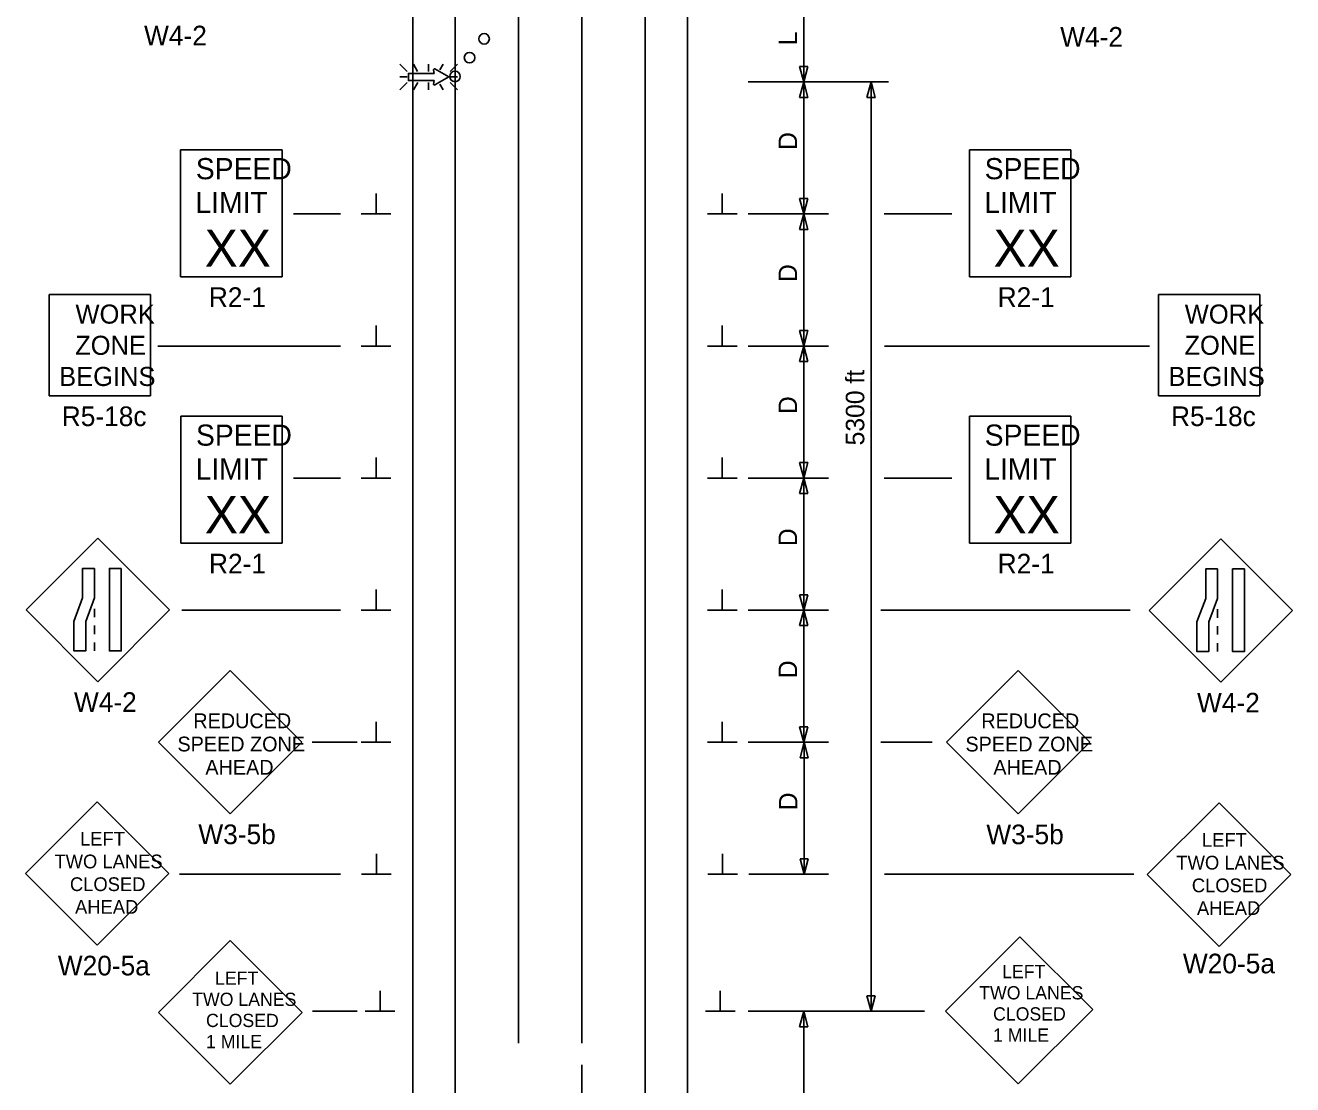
# Model space of a CAD drawing. Extents: x 16553 to 18478, y 5759 to 7026.
# Drawn here: x 16725.1 to 17204.7, y 6181.4 to 6582.5 of the extents above; entities that cross this region are included whole.
import ezdxf

# ---------------------------------------------------------------- set-up
doc = ezdxf.new("R2010")
doc.units = 0
for name, color, linetype in [('ALI_LEGAL_EX', 7, 'Continuous'), ('PAVT_EDGE_EX', 7, 'Continuous'), ('TRAFFIC_SIGNS_PR', 7, 'Continuous'), ('TYPICAL_TEXT_DIMEN_PR', 7, 'Continuous')]:
    doc.layers.add(name, color=color, linetype=linetype)

msp = doc.modelspace()

# ---------------------------------------------------------------- linework, layer by layer
at = {"layer": 'ALI_LEGAL_EX'}
for p, q in [((16911.66, 7026.35), (16911.66, 6197.16)), ((16935.66, 7026.35), (16935.66, 6197.16)), ((16935.66, 7026.35), (16935.66, 6197.16))]:
    msp.add_line(p, q, dxfattribs=at)
for points in [[(16911.66, 6526.35), (16911.66, 6501.35)], [(16935.66, 6526.35), (16935.66, 6501.35)], [(16911.66, 6426.35), (16911.66, 6401.35)], [(16935.66, 6426.35), (16935.66, 6401.35)], [(16911.66, 6326.35), (16911.66, 6301.35)], [(16935.66, 6326.35), (16935.66, 6301.35)], [(16911.66, 6226.35), (16911.66, 6201.35)], [(16935.66, 6226.35), (16935.66, 6201.35)], [(16935.66, 6163.99), (16935.66, 6188.99)]]:
    msp.add_lwpolyline(points, dxfattribs=at)
at = {"layer": 'PAVT_EDGE_EX'}
for p, q in [((16871.66, 6926.66), (16871.66, 6223.96)), ((16887.66, 6926.66), (16887.66, 6223.96)), ((16959.66, 6926.66), (16959.66, 6223.96)), ((16975.66, 6926.66), (16975.66, 6223.96)), ((16871.66, 6223.96), (16871.66, 6146.79)), ((16887.66, 6223.96), (16887.66, 6146.8)), ((16959.66, 6223.96), (16959.66, 6146.8)), ((16975.66, 6223.96), (16975.66, 6146.8))]:
    msp.add_line(p, q, dxfattribs=at)
at = {"layer": 'TRAFFIC_SIGNS_PR'}
for p, q in [((16869.6, 6564.95), (16866.78, 6567.77)), ((16871.9, 6567.77), (16873.52, 6564.95)), ((16877.68, 6564.95), (16877.68, 6567.77)), ((16883.15, 6567.77), (16881.94, 6565.68)), ((16888.59, 6567.77), (16885.77, 6564.95)), ((16869.6, 6562.92), (16866.78, 6562.92)), ((16885.77, 6562.92), (16888.59, 6562.92)), ((16869.6, 6560.88), (16866.78, 6558.06)), ((16873.55, 6560.88), (16871.92, 6558.06)), ((16877.68, 6560.88), (16877.68, 6558.06)), ((16881.87, 6560.25), (16883.13, 6558.06)), ((16888.59, 6558.07), (16885.77, 6560.88)), ((16783.81, 6535.36), (16822.25, 6535.36)), ((16783.81, 6487.3), (16783.81, 6535.36)), ((16822.25, 6487.3), (16822.25, 6535.36)), ((17082.32, 6535.36), (17120.77, 6535.36)), ((17082.32, 6487.3), (17082.32, 6535.36)), ((17120.77, 6487.3), (17120.77, 6535.36)), ((16783.81, 6487.3), (16822.25, 6487.3)), ((17082.32, 6487.3), (17120.77, 6487.3)), ((16734.03, 6442.19), (16734.03, 6480.59)), ((16734.03, 6480.59), (16772.43, 6480.59)), ((16772.43, 6442.19), (16772.43, 6480.59)), ((17153.83, 6442.19), (17153.83, 6480.59)), ((17153.83, 6480.59), (17192.23, 6480.59)), ((17192.23, 6442.19), (17192.23, 6480.59)), ((16734.03, 6442.19), (16772.43, 6442.19)), ((17153.83, 6442.19), (17192.23, 6442.19)), ((16783.86, 6434.49), (16822.31, 6434.49)), ((16783.86, 6386.43), (16783.86, 6434.49)), ((16822.31, 6386.43), (16822.31, 6434.49)), ((17082.32, 6434.49), (17120.77, 6434.49)), ((17082.32, 6386.43), (17082.32, 6434.49)), ((17120.77, 6386.43), (17120.77, 6434.49)), ((16752.49, 6388.29), (16725.34, 6361.14)), ((16779.64, 6361.14), (16752.49, 6388.29)), ((16783.86, 6386.43), (16822.31, 6386.43)), ((17082.32, 6386.43), (17120.77, 6386.43)), ((17177.51, 6388.07), (17150.35, 6360.92)), ((17204.66, 6360.92), (17177.51, 6388.07)), ((16725.34, 6361.14), (16752.49, 6333.98)), ((16751.24, 6361.63), (16751.24, 6358.43)), ((16752.49, 6333.98), (16779.64, 6361.14)), ((17150.35, 6360.92), (17177.51, 6333.77)), ((17176.26, 6361.41), (17176.26, 6358.21)), ((17177.51, 6333.77), (17204.66, 6360.92)), ((16751.24, 6355.23), (16751.24, 6352.03)), ((17176.26, 6355.01), (17176.26, 6351.81)), ((16751.24, 6348.83), (16751.24, 6345.63)), ((17176.26, 6348.61), (17176.26, 6345.41)), ((16802.58, 6338.23), (16775.42, 6311.08)), ((16829.73, 6311.08), (16802.58, 6338.23)), ((17100.79, 6338.22), (17073.64, 6311.07)), ((17127.94, 6311.07), (17100.79, 6338.22)), ((16775.42, 6311.08), (16802.58, 6283.93)), ((16802.58, 6283.93), (16829.73, 6311.08)), ((17073.64, 6311.07), (17100.79, 6283.91)), ((17100.79, 6283.91), (17127.94, 6311.07)), ((16752.21, 6288.55), (16725.06, 6261.39)), ((16779.37, 6261.39), (16752.21, 6288.55)), ((17176.79, 6288.09), (17149.64, 6260.94)), ((17203.94, 6260.94), (17176.79, 6288.09)), ((16725.06, 6261.39), (16752.21, 6234.24)), ((16752.21, 6234.24), (16779.37, 6261.39)), ((17149.64, 6260.94), (17176.79, 6233.79)), ((17176.79, 6233.79), (17203.94, 6260.94)), ((16802.61, 6235.96), (16775.43, 6208.77)), ((16829.8, 6208.77), (16802.61, 6235.96)), ((17101.44, 6237.43), (17073.26, 6209.25)), ((17129.01, 6209.87), (17101.44, 6237.43)), ((16775.43, 6208.77), (16802.61, 6181.58)), ((16802.61, 6181.58), (16829.8, 6208.77)), ((17073.26, 6209.25), (17100.83, 6181.69)), ((17100.83, 6181.69), (17129.01, 6209.87))]:
    msp.add_line(p, q, dxfattribs=at)
for points in [[(16880.01, 6559.9), (16885.32, 6562.92), (16880.01, 6565.96)], [(16879.51, 6565.6), (16879.74, 6564.3), (16870.02, 6564.3), (16870.02, 6561.56), (16879.74, 6561.56), (16879.51, 6560.26)]]:
    msp.add_lwpolyline(points, dxfattribs=at)
for points in [[(16751.24, 6376.87), (16751.24, 6365.69), (16747.9, 6356.81), (16747.9, 6345.63), (16743.41, 6345.63), (16743.41, 6356.81), (16746.75, 6365.69), (16746.75, 6376.87)], [(16761.38, 6376.87), (16761.38, 6345.63), (16756.89, 6345.63), (16756.89, 6376.87)], [(17176.26, 6376.66), (17176.26, 6365.48), (17172.92, 6356.59), (17172.92, 6345.41), (17168.42, 6345.41), (17168.42, 6356.59), (17171.77, 6365.48), (17171.77, 6376.66)], [(17186.4, 6376.66), (17186.4, 6345.41), (17181.9, 6345.41), (17181.9, 6376.66)]]:
    msp.add_lwpolyline(points, close=True, dxfattribs=at)
for centre in [(16898.67, 6577.37), (16893.17, 6570.24), (16887.67, 6563.12)]:
    msp.add_circle(centre, 2, dxfattribs=at)
for centre, start, end in [((16879.85, 6565.66), 61.4833, 189.9593), ((16879.85, 6560.2), 170.7308, 298.8916)]:
    msp.add_arc(centre, 0.341, start, end, dxfattribs=at)
at = {"layer": 'TYPICAL_TEXT_DIMEN_PR'}
for p, q in [((17019.66, 6561.07), (17019.66, 6591.63)), ((17019.66, 6561.07), (17018.09, 6566.93)), ((17018.09, 6566.93), (17019.66, 6566.93)), ((17019.66, 6566.93), (17021.23, 6566.93)), ((17021.23, 6566.93), (17019.66, 6561.07)), ((17051.71, 6561.07), (16998.66, 6561.07)), ((17018.09, 6555.21), (17019.66, 6561.07)), ((17019.66, 6561.07), (17019.66, 6511.07)), ((17019.66, 6561.07), (17021.23, 6555.21)), ((17043.53, 6555.21), (17045.1, 6561.07)), ((17045.1, 6561.07), (17045.1, 6209.23)), ((17045.1, 6561.07), (17046.67, 6555.21)), ((17019.66, 6555.21), (17018.09, 6555.21)), ((17021.23, 6555.21), (17019.66, 6555.21)), ((17045.1, 6555.21), (17043.53, 6555.21)), ((17046.67, 6555.21), (17045.1, 6555.21)), ((16857.78, 6511.07), (16857.78, 6518.85)), ((16988.79, 6511.07), (16988.79, 6518.85)), ((17019.66, 6511.07), (17018.09, 6516.93)), ((17018.09, 6516.93), (17019.66, 6516.93)), ((17019.66, 6516.93), (17021.23, 6516.93)), ((17021.23, 6516.93), (17019.66, 6511.07)), ((16844.35, 6511.07), (16826.6, 6511.07)), ((16863.4, 6511.07), (16852.15, 6511.07)), ((16994.41, 6511.07), (16983.16, 6511.07)), ((17029.05, 6511.07), (16998.66, 6511.07)), ((17018.09, 6505.21), (17019.66, 6511.07)), ((17019.66, 6511.07), (17019.66, 6461.07)), ((17019.66, 6511.07), (17021.23, 6505.21)), ((17075.66, 6511.07), (17050.1, 6511.07)), ((17019.66, 6505.21), (17018.09, 6505.21)), ((17021.23, 6505.21), (17019.66, 6505.21)), ((16857.78, 6461.07), (16857.78, 6468.85)), ((16988.79, 6461.07), (16988.79, 6468.85)), ((17019.66, 6461.07), (17018.09, 6466.93)), ((17018.09, 6466.93), (17019.66, 6466.93)), ((17019.66, 6466.93), (17021.23, 6466.93)), ((17021.23, 6466.93), (17019.66, 6461.07)), ((16844.35, 6461.07), (16775.18, 6461.07)), ((16863.4, 6461.07), (16852.15, 6461.07)), ((16994.41, 6461.07), (16983.16, 6461.07)), ((17029.05, 6461.07), (16998.66, 6461.07)), ((17018.09, 6455.21), (17019.66, 6461.07)), ((17019.66, 6461.07), (17019.66, 6411.07)), ((17019.66, 6461.07), (17021.23, 6455.21)), ((17150.53, 6461.07), (17050.16, 6461.07)), ((17019.66, 6455.21), (17018.09, 6455.21)), ((17021.23, 6455.21), (17019.66, 6455.21)), ((16857.78, 6411.07), (16857.78, 6418.85)), ((16988.79, 6411.07), (16988.79, 6418.85)), ((17019.66, 6411.07), (17018.09, 6416.93)), ((17018.09, 6416.93), (17019.66, 6416.93)), ((17019.66, 6416.93), (17021.23, 6416.93)), ((17021.23, 6416.93), (17019.66, 6411.07)), ((16844.35, 6411.07), (16826.6, 6411.07)), ((16863.4, 6411.07), (16852.15, 6411.07)), ((16994.41, 6411.07), (16983.16, 6411.07)), ((17029.05, 6411.07), (16998.66, 6411.07)), ((17018.09, 6405.21), (17019.66, 6411.07)), ((17019.66, 6411.07), (17019.66, 6361.07)), ((17019.66, 6411.07), (17021.23, 6405.21)), ((17075.66, 6411.07), (17050.1, 6411.07)), ((17019.66, 6405.21), (17018.09, 6405.21)), ((17021.23, 6405.21), (17019.66, 6405.21)), ((16857.78, 6361.07), (16857.78, 6368.85)), ((16988.79, 6361.07), (16988.79, 6368.85)), ((17019.66, 6361.07), (17018.09, 6366.93)), ((17018.09, 6366.93), (17019.66, 6366.93)), ((17019.66, 6366.93), (17021.23, 6366.93)), ((17021.23, 6366.93), (17019.66, 6361.07)), ((16844.35, 6361.07), (16784.31, 6361.07)), ((16863.4, 6361.07), (16852.15, 6361.07)), ((16994.41, 6361.07), (16983.16, 6361.07)), ((17029.05, 6361.07), (16998.66, 6361.07)), ((17018.09, 6355.21), (17019.66, 6361.07)), ((17019.66, 6361.07), (17019.66, 6311.07)), ((17019.66, 6361.07), (17021.23, 6355.21)), ((17143.12, 6361.07), (17048.84, 6361.07)), ((17019.66, 6355.21), (17018.09, 6355.21)), ((17021.23, 6355.21), (17019.66, 6355.21)), ((16857.78, 6311.07), (16857.78, 6318.85)), ((16988.79, 6311.07), (16988.79, 6318.85)), ((17019.66, 6311.07), (17018.09, 6316.93)), ((17018.09, 6316.93), (17019.66, 6316.93)), ((17019.66, 6316.93), (17021.23, 6316.93)), ((17021.23, 6316.93), (17019.66, 6311.07)), ((16833.6, 6311.07), (16850.58, 6311.07)), ((16863.4, 6311.07), (16852.15, 6311.07)), ((16994.41, 6311.07), (16983.16, 6311.07)), ((17029.05, 6311.07), (16998.66, 6311.07)), ((17018.23, 6305.21), (17019.8, 6311.07)), ((17019.8, 6311.07), (17019.8, 6261.07)), ((17019.8, 6311.07), (17021.37, 6305.21)), ((17068.24, 6311.07), (17048.84, 6311.07)), ((17019.8, 6305.21), (17018.23, 6305.21)), ((17021.37, 6305.21), (17019.8, 6305.21)), ((16857.92, 6261.07), (16857.92, 6268.85)), ((16988.93, 6261.07), (16988.93, 6268.85)), ((17019.8, 6261.07), (17018.23, 6266.93)), ((17018.23, 6266.93), (17019.8, 6266.93)), ((17019.8, 6266.93), (17021.37, 6266.93)), ((17021.37, 6266.93), (17019.8, 6261.07)), ((16844.35, 6261.07), (16783.44, 6261.07)), ((16863.54, 6261.07), (16852.29, 6261.07)), ((16994.55, 6261.07), (16983.3, 6261.07)), ((17029.05, 6261.07), (16998.8, 6261.07)), ((17144.54, 6261.07), (17050.16, 6261.07)), ((16859.29, 6209.23), (16859.29, 6217.01)), ((16988.04, 6209.23), (16988.04, 6217.01)), ((17045.1, 6209.23), (17043.53, 6215.09)), ((17043.53, 6215.09), (17045.1, 6215.09)), ((17045.1, 6215.09), (17046.67, 6215.09)), ((17046.67, 6215.09), (17045.1, 6209.23)), ((16833.74, 6209.23), (16850.58, 6209.23)), ((16853.66, 6209.23), (16864.91, 6209.23)), ((16993.66, 6209.23), (16982.41, 6209.23)), ((17065.32, 6209.23), (16998.66, 6209.23)), ((17018.09, 6203.36), (17019.66, 6209.23)), ((17019.66, 6209.23), (17019.66, 6109.23)), ((17019.66, 6209.23), (17021.24, 6203.36)), ((17019.66, 6203.36), (17018.09, 6203.36)), ((17021.24, 6203.36), (17019.66, 6203.36))]:
    msp.add_line(p, q, dxfattribs=at)

# ---------------------------------------------------------------- texts
at = {"layer": 'TRAFFIC_SIGNS_PR'}
for s, height, p in [('W4-2', 7.44, (16769.99, 6574.89)), ('W4-2', 7.44, (17116.69, 6574.4)), ('SPEED', 8.01, (16789.58, 6524.21)), ('SPEED', 8.01, (17088.1, 6524.21)), ('LIMIT', 8.01, (16789.42, 6511.4)), ('LIMIT', 8.01, (17087.93, 6511.4)), ('XX', 14.048, (16792.93, 6491.07)), ('XX', 14.048, (17091.45, 6491.07)), ('R2-1', 7.449, (16794.5, 6475.85)), ('R2-1', 7.449, (17093.01, 6475.85)), ('WORK', 7.217, (16744.03, 6469.55)), ('WORK', 7.217, (17163.83, 6469.55)), ('ZONE', 7.217, (16743.91, 6457.74)), ('ZONE', 7.217, (17163.71, 6457.74)), ('BEGINS', 7.217, (16737.84, 6445.94)), ('BEGINS', 7.217, (17157.64, 6445.94)), ('R5-18c', 7.44, (16738.84, 6430.75)), ('R5-18c', 7.44, (17158.64, 6430.75)), ('SPEED', 8.01, (16789.63, 6423.33)), ('SPEED', 8.01, (17088.1, 6423.33)), ('LIMIT', 8.01, (16789.47, 6410.52)), ('LIMIT', 8.01, (17087.93, 6410.52)), ('XX', 14.048, (16792.98, 6390.19)), ('XX', 14.048, (17091.45, 6390.19)), ('R2-1', 7.449, (16794.55, 6374.97)), ('R2-1', 7.449, (17093.01, 6374.97)), ('W4-2', 7.44, (16743.45, 6322.55)), ('W4-2', 7.44, (17168.46, 6322.33)), ('REDUCED', 5.6, (16788.63, 6316.39)), ('REDUCED', 5.6, (17086.85, 6316.37)), ('SPEED ZONE', 5.6, (16782.63, 6307.59)), ('SPEED ZONE', 5.6, (17080.84, 6307.57)), ('AHEAD', 5.6, (16793.19, 6298.79)), ('AHEAD', 5.6, (17091.4, 6298.77)), ('W3-5b', 7.44, (16790.53, 6272.49)), ('W3-5b', 7.44, (17088.74, 6272.47)), ('LEFT', 5.2, (16745.75, 6271.93)), ('LEFT', 5.2, (17170.33, 6271.48)), ('TWO LANES', 5.2, (16736.07, 6263.33)), ('TWO LANES', 5.2, (17160.65, 6262.88)), ('CLOSED', 5.2, (16741.93, 6254.73)), ('CLOSED', 5.2, (17166.5, 6254.28)), ('AHEAD', 5.2, (16743.87, 6246.13)), ('AHEAD', 5.2, (17168.45, 6245.68)), ('W20-5a', 7.44, (16737.35, 6222.8)), ('W20-5a', 7.44, (17163.13, 6223.58)), ('LEFT', 5.006, (17094.7, 6221.73)), ('LEFT', 5.006, (16796.85, 6219.26)), ('TWO LANES', 5.006, (16788.2, 6211.25)), ('TWO LANES', 5.006, (17086.04, 6213.72)), ('CLOSED', 5.006, (16793.44, 6203.25)), ('CLOSED', 5.006, (17091.28, 6205.72)), ('1 MILE', 5.006, (17091.27, 6197.71)), ('1 MILE', 5.006, (16793.43, 6195.24))]:
    msp.add_text(s, height=height, dxfattribs=at).set_placement(p)
at = {"layer": 'TYPICAL_TEXT_DIMEN_PR'}
for s, p in [('L', (17017.1, 6574.93)), ('D', (17017.11, 6535.29)), ('D', (17017.11, 6485.29)), ('5300 ft', (17042.55, 6423.43)), ('D', (17017.11, 6435.29)), ('D', (17017.11, 6385.29)), ('D', (17017.11, 6335.29)), ('D', (17017.24, 6285.29))]:
    msp.add_text(s, height=7, rotation=90, dxfattribs=at).set_placement(p)

doc.saveas('drawing.dxf')
